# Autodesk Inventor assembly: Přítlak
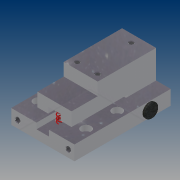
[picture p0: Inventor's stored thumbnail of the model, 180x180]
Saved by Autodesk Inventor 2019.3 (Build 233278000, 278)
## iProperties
Created: 2019-01
Part Number: Přítlak
Material: Všeobecné
Document SubType Name: Assembly
Designer: B-hon
Author: B-hon
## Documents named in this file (7)
- C:\Users\B-hon\OneDrive\Plocha\Bakalářka22\Přítlak\Levý\Přítlak2h.iam
- C:\Users\B-hon\OneDrive\Plocha\Bakalářka22\Přítlak\Levý\Příruba vozíku2h.ipt
- C:\Users\B-hon\OneDrive\Plocha\Bakalářka22\Přítlak\Levý\Příruba desky2h.ipt
- C:\Users\B-hon\OneDrive\Documents\Inventor\Content Center Files\R2019\cs-CZ\BS EN 22 341  B\ISO 2341 - B - 8 x 70BS EN.ipt
- C:\Users\B-hon\OneDrive\Documents\Inventor\Content Center Files\R2019\cs-CZ\CSN EN ISO 1234\CSN EN ISO 1234 - 2x16 x 10 - 9.ipt
- C:\Users\B-hon\OneDrive\Documents\Inventor\Content Center Files\R2019\cs-CZ\CSN EN ISO 2338\ISO 2338 - 6 h8 x 20CSN EN.ipt
- C:\Users\B-hon\OneDrive\Plocha\Bakalářka22\Přítlak\Levý\Přítlak2h\Design Accelerator\Tlačná pružina1.iam
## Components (6 placed, 6 different names)
1. Příruba vozíku2h:1 — Vložit:1, Úhel:1, Vložit:4, Proti sobě:4, Proti sobě:5
2. Příruba desky2h:1 — Vložit:1, Úhel:1, Vložit:3
3. BS EN 22341 B B - 8 x 70:1 — Proti sobě:3, Vložit:4
4. CSN EN ISO 1234 2x16:1 — Proti sobě:3
5. CSN EN ISO 2338 6 h8 x 20:1 — Vložit:3
6. Tlačná pružina:1 [sub-assembly] — Proti sobě:4, Proti sobě:5
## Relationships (7: Insert 3, Mate 3, Angle 1)
- Vložit:1 [Insert]: Příruba vozíku2h:1 ↔ Příruba desky2h:1
- Proti sobě:3 [Mate]: BS EN 22341 B B - 8 x 70:1 ↔ CSN EN ISO 1234 2x16:1
- Úhel:1 [Angle]: Příruba vozíku2h:1 ↔ Příruba desky2h:1
- Vložit:3 [Insert]: Příruba desky2h:1 ↔ CSN EN ISO 2338 6 h8 x 20:1
- Vložit:4 [Insert]: Příruba vozíku2h:1 ↔ BS EN 22341 B B - 8 x 70:1
- Proti sobě:4 [Mate]: Příruba vozíku2h:1 ↔ Tlačná pružina:1
- Proti sobě:5 [Mate]: Příruba vozíku2h:1 ↔ Tlačná pružina:1
